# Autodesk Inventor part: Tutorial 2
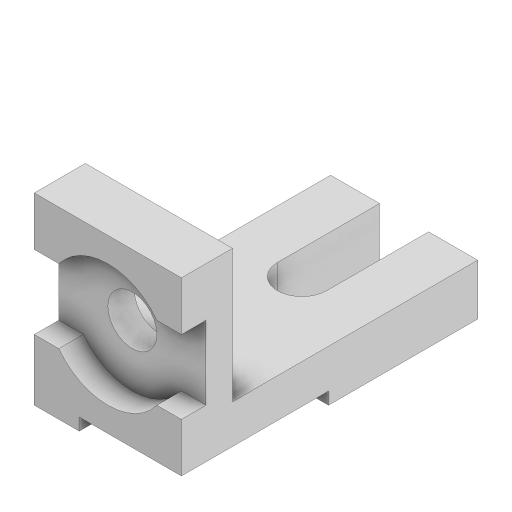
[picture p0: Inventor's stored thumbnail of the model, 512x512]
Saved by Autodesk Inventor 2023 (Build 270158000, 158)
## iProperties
Created: 2021-03
Part Number: Tutorial 2
Material: Generic
Document SubType Name: Modeling
Designer: ASUS Laptop
Density: 1 g/cm^3
Appearance: Default
Author: ASUS Laptop
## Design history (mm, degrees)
sketch "Sketch1"
  geometry: L1 (0, 0)-(90, 0); L2 (90, 0)-(90, -25); L3 (90, -25)-(25, -25); L4 (25, -25)-(25, -145); L5 (25, -145)-(0, -145); L6 (0, -145)-(0, 0)
  constraints: 12 end point, 6 perpendicular, 1 horizontal
  dimensions: "d0" = 145 distance of L5.end L1.start; "d1" = 90 distance between parallel lines of L2 L6; "d2" = 25 distance of L1.end L2.end
extrude "Extrusion1" new body sketch "Sketch1" stored distance "d4" = 72; taper "d5" = 0 deg
sketch "Sketch2"
  geometry: L1 (0, 0)-(72, 0); L2 (72, 0)-(72, 6); L3 (72, 6)-(0, 6); L4 (0, 6)-(0, 0)
  constraints: 8 end point, 2 parallel, 1 horizontal, 1 perpendicular
  dimensions: "d6" = 72 distance of L1.start L1.end; "d7" = 6 distance between parallel lines of L1 L3
extrude "Extrusion2" cut sketch "Sketch2" distance "d8" = 50; taper "d9" = 0 deg
sketch "Sketch3"
  geometry: L1 (12, -24)-(0, -24); L2 (0, -90)-(0, 0) reference; L3 (0, -24)-(0, -60); L4 (0, -60)-(12, -60); L5 (60, -24)-(72, -24); L6 (72, 0)-(72, -84) reference; L7 (72, -24)-(72, -60); L8 (72, -60)-(60, -60); L9 (72, -90)-(22, -90) reference; L10 (0, -90)-(22, -90) reference; A1 r 30 centre (36, -42) between (12, -60) and (60, -60); A2 r 30 centre (36, -42) between (60, -24) and (12, -24); 3 further points
  constraints: 12 end point, 4 point on circle, 4 point on line, 2 centre point, 2 perpendicular, 1 collinear, 1 concentric, 1 horizontal, 1 parallel, 1 vertical
  dimensions: "d10" = 30 radius of A2; "d11" = 36 distance from line of A1.centre L2; "d12" = 48 distance from line of L9 A1.centre; "d13" = 30 distance between parallel lines of L4 L10; "d14" = 36 distance between parallel lines of L4 L1
extrude "Extrusion3" cut sketch "Sketch3" distance "d15" = 12; taper "d16" = 0 deg
sketch "Sketch4"
  geometry: C1 r 12 at (36, -42); A1 r 30 centre (36, -42) between (60, -24) and (12, -24) reference; 1 further point
  constraints: 1 centre point, 1 concentric
  dimensions: "d17" = 24 diameter of C1
extrude "Extrusion4" cut sketch "Sketch4" extent not by distance; stored distance "d18" = 10; taper "d19" = 0 deg
sketch "Sketch5"
  geometry: L1 (24, 120)-(24, 70); L2 (48, 70)-(48, 120); L3 (48, 120)-(24, 120); L4 (72, 120)-(72, 0) reference; A1 r 12 centre (36, 70) between (24, 70) and (48, 70); 2 further points
  constraints: 6 end point, 2 point on circle, 2 tangent, 1 centre point, 1 parallel, 1 perpendicular, 1 point on line, 1 vertical
  dimensions: "d20" = 36 distance from line of A1.centre L4; "d21" = 12 radius of A1; "d22" = 50 distance of L2.start L2.end
extrude "Extrusion5" cut sketch "Sketch5" extent not by distance; stored distance "d23" = 0; taper "d24" = 0 deg
body "Solid1"
